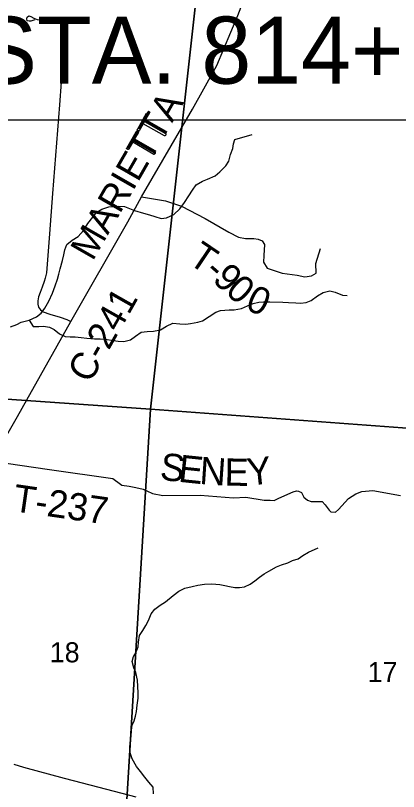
# Model space of a CAD drawing. Extents: x 0 to 34, y 0 to 22.
# Drawn here: x 6.181 to 6.981, y 15.611 to 17.231 of the extents above; entities that cross this region are included whole.
import ezdxf

# ---------------------------------------------------------------- set-up
doc = ezdxf.new("R2010")
doc.units = 0
for name, color, linetype in [('GM_X_Corporation', 7, 'Continuous'), ('GM_X_County_Road', 7, 'Continuous'), ('GM_X_County_Road_Text', 7, 'Continuous'), ('GM_X_Minor_River', 7, 'Continuous'), ('GM_X_Rail_Line', 7, 'Continuous'), ('GM_X_Section_Text', 7, 'Continuous'), ('GM_X_Township_Road', 7, 'Continuous'), ('GM_X_Township_Road_Text', 7, 'Continuous'), ('SH_Data', 7, 'Continuous'), ('SH_Text', 7, 'Continuous')]:
    doc.layers.add(name, color=color, linetype=linetype)

msp = doc.modelspace()

# ---------------------------------------------------------------- linework, layer by layer
at = {"layer": 'GM_X_Corporation'}
for points in [[(5.601, 17.4809), (6.5737, 17.4057), (6.463, 16.4089), (5.5235, 16.4744)], [(6.5737, 17.4057), (7.5885, 17.3345), (7.4964, 16.3324), (6.463, 16.4089)], [(5.5235, 16.4744), (6.463, 16.4089), (6.4021, 15.41), (6.1231, 15.4306), (6.1464, 15.8767), (5.4838, 15.928)], [(6.463, 16.4089), (7.4964, 16.3324), (7.434, 15.3319), (6.4021, 15.41)]]:
    msp.add_lwpolyline(points, close=True, dxfattribs=at)
at = {"layer": 'GM_X_County_Road'}
msp.add_lwpolyline([(6.132, 16.3005), (6.152, 16.3353), (6.1854, 16.3936), (6.205, 16.4288), (6.2965, 16.5923), (6.4152, 16.8002), (6.444, 16.8523), (6.5504, 17.0354), (6.6011, 17.1267), (6.6455, 17.2305), (6.6736, 17.3056)], dxfattribs=at)
at = {"layer": 'GM_X_County_Road_Text'}
for p, q in [((6.4354, 16.9927), (6.4548, 17.0267)), ((6.4576, 17.0266), (6.4576, 17.0266)), ((6.4132, 16.954), (6.4326, 16.988)), ((6.4354, 16.9879), (6.4354, 16.9879))]:
    msp.add_line(p, q, dxfattribs=at)
for points in [[(6.459, 17.0243), (6.4505, 17.0096), (6.4947, 16.9843)], [(6.4921, 16.9797), (6.4479, 17.005), (6.4395, 16.9904)], [(6.4368, 16.9856), (6.4284, 16.971), (6.4725, 16.9456)], [(6.4699, 16.941), (6.4257, 16.9663), (6.4173, 16.9517)]]:
    msp.add_lwpolyline(points, dxfattribs=at)
for points in [[(6.4548, 17.0267), (6.455, 17.0269), (6.4552, 17.0271)], [(6.4552, 17.0271), (6.4555, 17.0272), (6.4559, 17.0272)], [(6.4559, 17.0272), (6.4562, 17.0272), (6.4567, 17.0271)], [(6.4567, 17.0271), (6.4571, 17.0269), (6.4576, 17.0266)], [(6.4576, 17.0266), (6.4581, 17.0263), (6.4584, 17.026)], [(6.4584, 17.026), (6.4588, 17.0258), (6.4589, 17.0255)], [(6.4589, 17.0255), (6.4591, 17.0252), (6.4591, 17.0249)], [(6.4591, 17.0249), (6.4591, 17.0246), (6.459, 17.0243)], [(6.4326, 16.988), (6.4328, 16.9882), (6.4331, 16.9884)], [(6.4331, 16.9884), (6.4333, 16.9885), (6.4337, 16.9885)], [(6.4337, 16.9885), (6.434, 16.9885), (6.4345, 16.9884)], [(6.4345, 16.9884), (6.4349, 16.9882), (6.4354, 16.9879)], [(6.4352, 16.9921), (6.4352, 16.9924), (6.4354, 16.9927)], [(6.4354, 16.9916), (6.4352, 16.9919), (6.4352, 16.9921)], [(6.4359, 16.9909), (6.4356, 16.9913), (6.4354, 16.9916)], [(6.4354, 16.9879), (6.4359, 16.9877), (6.4363, 16.9874)], [(6.4368, 16.9903), (6.4363, 16.9906), (6.4359, 16.9909)], [(6.4363, 16.9874), (6.4366, 16.9871), (6.4367, 16.9868)], [(6.4367, 16.9868), (6.4369, 16.9865), (6.4369, 16.9862)], [(6.4377, 16.9899), (6.4373, 16.9901), (6.4368, 16.9903)], [(6.4385, 16.9898), (6.4381, 16.9898), (6.4377, 16.9899)], [(6.4391, 16.9899), (6.4388, 16.9898), (6.4385, 16.9898)], [(6.4395, 16.9904), (6.4393, 16.9901), (6.4391, 16.9899)], [(6.4369, 16.9862), (6.4369, 16.9859), (6.4368, 16.9856)], [(6.4926, 16.9795), (6.4923, 16.9795), (6.4921, 16.9797)], [(6.4931, 16.9798), (6.4928, 16.9796), (6.4926, 16.9795)], [(6.4937, 16.9804), (6.4933, 16.98), (6.4931, 16.9798)], [(6.4944, 16.9814), (6.494, 16.9808), (6.4937, 16.9804)], [(6.4949, 16.9826), (6.4948, 16.9821), (6.4944, 16.9814)], [(6.4947, 16.9843), (6.495, 16.9842), (6.4951, 16.9839)], [(6.4952, 16.9834), (6.4951, 16.9831), (6.4949, 16.9826)], [(6.4951, 16.9839), (6.4952, 16.9837), (6.4952, 16.9834)], [(6.413, 16.9535), (6.413, 16.9537), (6.4132, 16.954)], [(6.4132, 16.9529), (6.413, 16.9532), (6.413, 16.9535)], [(6.4137, 16.9523), (6.4134, 16.9526), (6.4132, 16.9529)], [(6.4146, 16.9517), (6.4141, 16.952), (6.4137, 16.9523)], [(6.4155, 16.9512), (6.4151, 16.9514), (6.4146, 16.9517)], [(6.4163, 16.9511), (6.4159, 16.9511), (6.4155, 16.9512)], [(6.4169, 16.9512), (6.4166, 16.9511), (6.4163, 16.9511)], [(6.4173, 16.9517), (6.4171, 16.9514), (6.4169, 16.9512)], [(6.4704, 16.9409), (6.4701, 16.9409), (6.4699, 16.941)], [(6.4709, 16.9411), (6.4706, 16.9409), (6.4704, 16.9409)], [(6.4715, 16.9417), (6.4711, 16.9413), (6.4709, 16.9411)], [(6.4722, 16.9427), (6.4718, 16.9421), (6.4715, 16.9417)], [(6.4727, 16.9439), (6.4726, 16.9434), (6.4722, 16.9427)], [(6.4725, 16.9456), (6.4728, 16.9455), (6.4729, 16.9453)], [(6.473, 16.9447), (6.4729, 16.9444), (6.4727, 16.9439)], [(6.4729, 16.9453), (6.473, 16.945), (6.473, 16.9447)]]:
    msp.add_open_spline(points, degree=2, dxfattribs=at)
at = {"layer": 'GM_X_Minor_River'}
for p, q in [((6.6362, 16.9628), (6.6389, 16.9723)), ((6.6389, 16.9723), (6.6749, 16.9824)), ((6.6346, 16.9529), (6.6362, 16.9628)), ((6.6265, 16.9268), (6.6296, 16.9408)), ((6.6296, 16.9408), (6.6346, 16.9529))]:
    msp.add_line(p, q, dxfattribs=at)
for points in [[(6.1703, 16.5813), (6.1836, 16.5862), (6.1931, 16.5907), (6.2094, 16.5952), (6.2249, 16.602), (6.2348, 16.6095), (6.2421, 16.6201), (6.2505, 16.6349), (6.2585, 16.6515), (6.2639, 16.6667), (6.2685, 16.6803), (6.2716, 16.6913), (6.2743, 16.7023), (6.2789, 16.7198), (6.2816, 16.7315), (6.2843, 16.7417), (6.2882, 16.7531), (6.2996, 16.7622), (6.3117, 16.7693), (6.3228, 16.7818), (6.332, 16.7966), (6.3422, 16.8098), (6.351, 16.8204), (6.3616, 16.8268), (6.3761, 16.8313), (6.3855, 16.8324), (6.3958, 16.8331), (6.4086, 16.832), (6.4294, 16.8235), (6.4484, 16.8182), (6.4605, 16.8151), (6.4722, 16.8112), (6.485, 16.8074), (6.4964, 16.8085), (6.5116, 16.8156), (6.5242, 16.8274), (6.5341, 16.8406), (6.5432, 16.8546), (6.5505, 16.866), (6.5581, 16.8777), (6.5714, 16.8852), (6.5817, 16.889), (6.5976, 16.8965), (6.6075, 16.9045), (6.62, 16.9169), (6.6265, 16.9268), (6.6296, 16.9408), (6.6346, 16.9529), (6.6362, 16.9628), (6.6389, 16.9723), (6.6749, 16.9824)], [(6.2094, 16.5952), (6.218, 16.5819), (6.2298, 16.5814), (6.2396, 16.5825), (6.2517, 16.5806), (6.2616, 16.5753), (6.2729, 16.5665), (6.2846, 16.5611), (6.2952, 16.56), (6.3058, 16.5603), (6.3183, 16.5591), (6.3297, 16.5575), (6.3459, 16.5563), (6.3581, 16.5563), (6.3679, 16.5555), (6.3857, 16.5524), (6.3955, 16.5509), (6.4069, 16.5501), (6.4209, 16.5542), (6.4316, 16.5617), (6.4433, 16.5697), (6.4562, 16.5715), (6.4691, 16.5718), (6.4835, 16.5748), (6.4961, 16.5824), (6.5094, 16.5888), (6.5241, 16.5872), (6.5366, 16.5868), (6.5465, 16.5882), (6.5616, 16.5908), (6.5715, 16.5935), (6.5856, 16.6025), (6.5992, 16.6119), (6.6087, 16.6153), (6.6273, 16.6164), (6.6375, 16.6167), (6.6531, 16.6193), (6.6652, 16.625), (6.677, 16.6299), (6.6891, 16.6325), (6.699, 16.6332), (6.7122, 16.6332), (6.7395, 16.6323), (6.7512, 16.6319), (6.766, 16.6311), (6.7762, 16.6307), (6.788, 16.6321), (6.7986, 16.6359), (6.8115, 16.6457), (6.8233, 16.6529), (6.8373, 16.6562), (6.8487, 16.6532), (6.8638, 16.6474), (6.8737, 16.6466)], [(6.4693, 15.6068), (6.4682, 15.6205), (6.4595, 15.6311), (6.4512, 15.641), (6.4418, 15.6528), (6.4335, 15.6634), (6.4244, 15.6793), (6.4207, 15.6922), (6.4195, 15.7032), (6.4203, 15.7131), (6.4222, 15.7267), (6.4234, 15.7389), (6.4246, 15.7495), (6.4291, 15.7589), (6.4314, 15.7688), (6.4333, 15.7786), (6.4349, 15.7912), (6.4372, 15.8063), (6.4368, 15.8173), (6.4365, 15.8302), (6.4358, 15.8439), (6.4324, 15.8594), (6.4279, 15.8697), (6.4245, 15.8829), (6.4275, 15.8928), (6.4329, 15.9026), (6.4371, 15.9136), (6.4375, 15.9231), (6.4398, 15.9368), (6.4466, 15.9474), (6.4531, 15.9576), (6.4584, 15.9682), (6.4645, 15.9822), (6.4717, 15.9921), (6.4831, 16), (6.494, 16.0072), (6.51, 16.0201), (6.5221, 16.0295), (6.5346, 16.036), (6.5498, 16.0394), (6.5615, 16.042), (6.5755, 16.0442), (6.5907, 16.0446), (6.6073, 16.0434), (6.6179, 16.0415), (6.6277, 16.0389), (6.6387, 16.0373), (6.6489, 16.0373), (6.6591, 16.0384), (6.6709, 16.0437), (6.6808, 16.0509), (6.6906, 16.0589), (6.7001, 16.0653), (6.7096, 16.0714), (6.7262, 16.0804), (6.7365, 16.0842), (6.7493, 16.0884), (6.7592, 16.0933), (6.7709, 16.0971), (6.7808, 16.1042), (6.7929, 16.1111), (6.8126, 16.1201)]]:
    msp.add_lwpolyline(points, dxfattribs=at)
at = {"layer": 'GM_X_Rail_Line'}
msp.add_lwpolyline([(6.433, 15.5994), (6.3555, 15.6195), (6.2831, 15.6388), (6.1987, 15.6613), (6.1782, 15.6677)], dxfattribs=at)
at = {"layer": 'GM_X_Township_Road'}
for points in [[(6.2216, 17.2215), (6.2171, 17.2206), (6.2129, 17.2187), (6.2093, 17.2187), (6.2057, 17.2198), (6.2046, 17.2236), (6.2055, 17.227), (6.2091, 17.2299), (6.2131, 17.2285), (6.219, 17.2255), (6.2264, 17.2221), (6.2674, 17.2202), (6.2738, 17.2181), (6.2784, 17.2143), (6.2826, 17.2084), (6.2843, 17.2012), (6.2839, 17.19), (6.2836, 17.186)], [(6.2836, 17.186), (6.2727, 17.0446), (6.2583, 16.8592), (6.252, 16.7753), (6.2467, 16.7027), (6.2454, 16.6935), (6.2431, 16.6823), (6.241, 16.676), (6.237, 16.6637), (6.2323, 16.6529), (6.2292, 16.6438), (6.2276, 16.6354), (6.2277, 16.6282), (6.2292, 16.6219), (6.2333, 16.6165), (6.2388, 16.6127), (6.2524, 16.6072), (6.2743, 16.6011), (6.2879, 16.5967), (6.2965, 16.5923)], [(6.444, 16.8523), (6.4943, 16.8441), (6.5276, 16.8331), (6.577, 16.8071), (6.6267, 16.7784), (6.6467, 16.768), (6.6614, 16.7651), (6.6785, 16.7653), (6.688, 16.7641), (6.6959, 16.7602), (6.7008, 16.7529)], [(6.7008, 16.7529), (6.6993, 16.7302), (6.6991, 16.7161), (6.7066, 16.7035), (6.7379, 16.6929), (6.7694, 16.6891), (6.7853, 16.6855), (6.799, 16.6873), (6.8085, 16.6932), (6.8084, 16.713), (6.8175, 16.7443)], [(6.132, 16.3005), (6.2523, 16.2831), (6.3842, 16.2647), (6.4005, 16.2524)], [(6.4005, 16.2524), (6.4029, 16.2506), (6.4184, 16.2483), (6.432, 16.2459), (6.4479, 16.2423), (6.4659, 16.2337)], [(6.4659, 16.2337), (6.4668, 16.2333), (6.4888, 16.2293), (6.5669, 16.2299), (6.6363, 16.2245), (6.6621, 16.2254), (6.7, 16.2196), (6.7125, 16.2191), (6.7213, 16.2186), (6.7308, 16.2238), (6.7609, 16.2364), (6.7674, 16.2386), (6.772, 16.2381), (6.778, 16.235), (6.7832, 16.2259), (6.7907, 16.2193), (6.7986, 16.2166), (6.8123, 16.2168), (6.821, 16.2167), (6.8274, 16.2094), (6.8356, 16.1983), (6.8397, 16.1952), (6.8488, 16.1944), (6.8557, 16.2), (6.8765, 16.2225), (6.8914, 16.2322), (6.9044, 16.2374), (6.9268, 16.2398), (6.9849, 16.2293)]]:
    msp.add_lwpolyline(points, dxfattribs=at)
at = {"layer": 'SH_Data'}
msp.add_line((7.9543, 17.0126), (6.0621, 17.0126), dxfattribs=at)

# ---------------------------------------------------------------- texts
at = {"layer": 'GM_X_County_Road_Text'}
for s, rotation, p in [('MARIETTA', 60.1557, (6.3421, 16.7165)), ('C-241', 60.4927, (6.3362, 16.4609))]:
    msp.add_text(s, height=0.05682, rotation=rotation, dxfattribs=at).set_placement(p)
at = {"layer": 'GM_X_Section_Text'}
for s, p in [('18', (6.2526, 15.8809)), ('17', (6.9163, 15.8398))]:
    msp.add_text(s, height=0.04186, rotation=0, dxfattribs=at).set_placement(p)
at = {"layer": 'GM_X_Township_Road_Text'}
for s, height, rotation, p in [('T', 0.0568, 326.0069, (6.539, 16.7152)), ('-', 0.0568, 318.8721, (6.5728, 16.6926)), ('9', 0.0568, 316.9544, (6.59, 16.6776)), ('0', 0.0568, 318.3312, (6.6167, 16.6527)), ('0', 0.0568, 335.3929, (6.6582, 16.6193)), ('S', 0.0568, 353.548, (6.4809, 16.2622)), ('E', 0.0568, 354.0934, (6.5196, 16.2579)), ('N', 0.0568, 356.1248, (6.5641, 16.2533)), ('Y', 0.0568, 6.0255, (6.6672, 16.2494)), ('E', 0.0568, 359.0073, (6.6171, 16.2498)), ('T-237', 0.05682, 351.8305, (6.1736, 16.1966))]:
    msp.add_text(s, height=height, rotation=rotation, dxfattribs=at).set_placement(p)
at = {"layer": 'SH_Text'}
msp.add_text('STA. 814+10 U.S. 23', height=0.14, dxfattribs=at).set_placement((6.1009, 17.0884))

doc.saveas('drawing.dxf')
